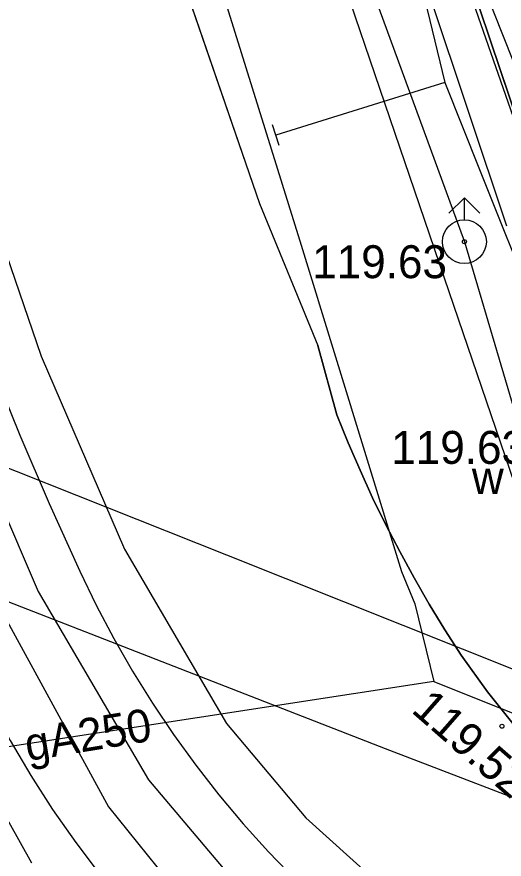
# Model space of a CAD drawing. Extents: x 6432121 to 6432331, y 5662538 to 5662686.
# Drawn here: x 6432274.79 to 6432285.88, y 5662571.21 to 5662590.39 of the extents above; entities that cross this region are included whole.
import ezdxf

# ---------------------------------------------------------------- set-up
doc = ezdxf.new("R2010")
doc.units = 0
for name, color, linetype in [('Warstwa 1', 7, 'Continuous'), ('Warstwa 12', 7, 'Continuous'), ('Warstwa 13', 7, 'Continuous'), ('Warstwa 14', 7, 'Continuous'), ('Warstwa 15', 7, 'Continuous'), ('Warstwa 20', 7, 'Continuous'), ('Warstwa 25', 7, 'Continuous'), ('Warstwa 37', 7, 'Continuous'), ('Warstwa 4', 7, 'Continuous'), ('Warstwa 5', 7, 'Continuous'), ('Warstwa 6', 7, 'Continuous'), ('Warstwa 8', 7, 'Continuous'), ('Warstwa 9', 7, 'Continuous')]:
    doc.layers.add(name, color=color, linetype=linetype)

msp = doc.modelspace()

# ---------------------------------------------------------------- linework, layer by layer
at = {"layer": 'Warstwa 1'}
msp.add_line((6432267.75, 5662642.76), (6432287.64, 5662583.69), dxfattribs=at)
msp.add_line((6432267.75, 5662642.76), (6432287.64, 5662583.69), dxfattribs=at)
at = {"layer": 'Warstwa 12'}
for points in [[(6432259.267, 5662681.053), (6432259.329, 5662671.143), (6432259.331, 5662662.919), (6432260.078, 5662660.682), (6432263.877, 5662649.208), (6432267.527, 5662638.022), (6432271.438, 5662626.054), (6432273.548, 5662619.652), (6432276.516, 5662610.473), (6432279.664, 5662600.926), (6432282.613, 5662591.736), (6432284.976, 5662585.268), (6432286.395, 5662580.459), (6432288.268, 5662574.665)], [(6432288.269, 5662573.47), (6432290.18, 5662576.365), (6432289.651, 5662577.89), (6432283.657, 5662595.089), (6432278.636, 5662609.529), (6432275.228, 5662619.384), (6432273.259, 5662625.008), (6432269.06, 5662637.307), (6432265.455, 5662647.676), (6432262.131, 5662657.28), (6432261.494, 5662659.216), (6432262.228, 5662660.626), (6432262.598, 5662661.472), (6432263.21, 5662662.431), (6432263.592, 5662662.793), (6432265.636, 5662665.038), (6432264.282, 5662671.637), (6432263.631, 5662675.181), (6432263.032, 5662678.117), (6432262.911, 5662681.053)], [(6432258.356, 5662662.998), (6432258.39, 5662658.398), (6432260.508, 5662651.738), (6432262.768, 5662644.481), (6432265.197, 5662636.781), (6432267.384, 5662629.75), (6432269.748, 5662622.257), (6432272.462, 5662613.493), (6432273.441, 5662610.386), (6432276.081, 5662601.737), (6432278.642, 5662593.628), (6432281.263, 5662585.188), (6432283.543, 5662577.76), (6432283.852, 5662577.022), (6432284.284, 5662575.255)], [(6432261.338, 5662662.021), (6432260.831, 5662661.256), (6432261.33, 5662655.003), (6432261.566, 5662651.833), (6432262.397, 5662649.473), (6432263.18, 5662647.177), (6432265.745, 5662639.575), (6432268.331, 5662631.988), (6432271.28, 5662623.264), (6432274.385, 5662614.242), (6432277.778, 5662604.216), (6432280.796, 5662595.387), (6432284.518, 5662584.444), (6432287.071, 5662576.95), (6432288.269, 5662573.47)], [(6432294.644, 5662569.974), (6432292.199, 5662571.213), (6432291.73, 5662571.359), (6432291.554, 5662571.691), (6432290.843, 5662575.72), (6432287.011, 5662587.057), (6432285.41, 5662591.097), (6432281.352, 5662603.627), (6432279.346, 5662609.722), (6432279.211, 5662610.184), (6432279.026, 5662610.616), (6432274.158, 5662623.936), (6432272.237, 5662630.449), (6432265.984, 5662647.596), (6432266.37, 5662648.378)], [(6432273.378, 5662628.56), (6432274.214, 5662626.373), (6432275.936, 5662621.592), (6432276.137, 5662621.121), (6432277.158, 5662615.29), (6432277.656, 5662613.21), (6432277.121, 5662611.091), (6432279.065, 5662604.892), (6432281.714, 5662603.797), (6432281.489, 5662600.828), (6432283.129, 5662594.282), (6432283.903, 5662591.502), (6432284.529, 5662588.89)], [(6432284.529, 5662588.89), (6432280.685, 5662587.694)], [(6432284.529, 5662588.89), (6432285.324, 5662586.912), (6432286.601, 5662583.708), (6432288.192, 5662579.261), (6432289.015, 5662577.532), (6432294.313, 5662575.121), (6432301.928, 5662571.798), (6432305.283, 5662570.247), (6432308.513, 5662568.879)], [(6432288.268, 5662574.665), (6432287.596, 5662574.929), (6432279.572, 5662578.128), (6432271.367, 5662581.39), (6432268.733, 5662580.715)], [(6432268.423, 5662579.446), (6432268.914, 5662579.286), (6432283.177, 5662573.724), (6432291.711, 5662570.445), (6432298.653, 5662567.696), (6432305.047, 5662565.259), (6432317.636, 5662560.353), (6432325.976, 5662557.133)], [(6432284.284, 5662575.255), (6432271.673, 5662573.315), (6432269.061, 5662572.854)], [(6432284.284, 5662575.255), (6432291.672, 5662572.293), (6432300.987, 5662568.554), (6432313.035, 5662563.657), (6432322.464, 5662559.942), (6432325.786, 5662558.712), (6432325.976, 5662558.636)]]:
    msp.add_lwpolyline(points, dxfattribs=at)
at = {"layer": 'Warstwa 14'}
msp.add_circle((6432284.976, 5662585.268), 0.045, dxfattribs=at)
at = {"layer": 'Warstwa 20'}
msp.add_line((6432280.759, 5662587.455), (6432280.611, 5662587.933), dxfattribs=at)
at = {"layer": 'Warstwa 25'}
msp.add_circle((6432285.831, 5662574.233), 0.045, dxfattribs=at)
at = {"layer": 'Warstwa 37'}
for points in [[(6432270.98, 5662592.032), (6432271.449, 5662590.408), (6432271.947, 5662588.793), (6432272.474, 5662587.187), (6432273.03, 5662585.59), (6432273.613, 5662584.003), (6432274.225, 5662582.427), (6432274.865, 5662580.863), (6432275.532, 5662579.309), (6432276.227, 5662577.768)], [(6432276.227, 5662577.768), (6432276.6, 5662576.994), (6432277.001, 5662576.234), (6432277.428, 5662575.489), (6432277.882, 5662574.759), (6432278.361, 5662574.046), (6432278.865, 5662573.35), (6432279.393, 5662572.672), (6432279.945, 5662572.013), (6432280.52, 5662571.375)], [(6432273.41, 5662576.382), (6432273.789, 5662575.542), (6432274.199, 5662574.716), (6432274.639, 5662573.907), (6432275.109, 5662573.114), (6432275.607, 5662572.339), (6432276.134, 5662571.582), (6432276.688, 5662570.846), (6432277.269, 5662570.13), (6432277.876, 5662569.437)], [(6432280.52, 5662571.375), (6432281.172, 5662570.694), (6432281.851, 5662570.041), (6432282.557, 5662569.417), (6432283.288, 5662568.823), (6432284.044, 5662568.259), (6432284.822, 5662567.728), (6432285.621, 5662567.229), (6432286.441, 5662566.763), (6432287.279, 5662566.333)]]:
    msp.add_lwpolyline(points, dxfattribs=at)
at = {"layer": 'Warstwa 4'}
for points in [[(6432284.622, 5662585.914), (6432284.976, 5662586.268)], [(6432285.33, 5662585.914), (6432284.976, 5662586.268)], [(6432284.976, 5662585.768), (6432284.976, 5662586.268)]]:
    msp.add_lwpolyline(points, dxfattribs=at)
msp.add_circle((6432284.976, 5662585.268), 0.5, dxfattribs=at)
at = {"layer": 'Warstwa 5'}
msp.add_line((6432281.622, 5662598.544), (6432285.935, 5662585.632), dxfattribs=at)
at = {"layer": 'Warstwa 6'}
msp.add_lwpolyline([(6432278.892, 5662645.679), (6432279.29, 5662646.39), (6432267.75, 5662642.76), (6432287.64, 5662583.69), (6432294.025, 5662578.332), (6432295.024, 5662576.599), (6432295.196, 5662575.127), (6432301.46, 5662572.69), (6432295.88, 5662579.43), (6432289.26, 5662614.9)], close=True, dxfattribs=at)
for points in [[(6432295.199, 5662556.053), (6432289.811, 5662577.223), (6432287.64, 5662583.69), (6432267.75, 5662642.76), (6432246.69, 5662636.13), (6432263.163, 5662588.197), (6432269.007, 5662560.534), (6432269.756, 5662556.053)], [(6432261.53, 5662642.45), (6432261.725, 5662641.888), (6432263.054, 5662637.661), (6432266.526, 5662627.159), (6432271.921, 5662611.052), (6432274.366, 5662604.334), (6432277.03, 5662595.697), (6432280.318, 5662586.138), (6432281.64, 5662582.902)], [(6432282.071, 5662581.326), (6432281.64, 5662582.902)], [(6432284.904, 5662575.849), (6432284.534, 5662576.428), (6432284.178, 5662577.014), (6432283.835, 5662577.609), (6432283.506, 5662578.211), (6432283.19, 5662578.821), (6432282.889, 5662579.437), (6432282.602, 5662580.061), (6432282.329, 5662580.691), (6432282.071, 5662581.326)], [(6432291.638, 5662569.69), (6432290.756, 5662570.209), (6432289.902, 5662570.773), (6432289.079, 5662571.381), (6432288.289, 5662572.032), (6432287.534, 5662572.722), (6432286.816, 5662573.451), (6432286.137, 5662574.217), (6432285.499, 5662575.017), (6432284.904, 5662575.849)]]:
    msp.add_lwpolyline(points, dxfattribs=at)
at = {"layer": 'Warstwa 8'}
for p, q in [((6432277.03, 5662595.697), (6432280.318, 5662586.138)), ((6432272.015, 5662592.39), (6432275.347, 5662582.659)), ((6432272.015, 5662592.39), (6432275.347, 5662582.659)), ((6432280.318, 5662586.138), (6432281.64, 5662582.902)), ((6432281.64, 5662582.902), (6432282.071, 5662581.326)), ((6432275.347, 5662582.659), (6432277.243, 5662578.265)), ((6432275.347, 5662582.659), (6432277.243, 5662578.265)), ((6432273.307, 5662581.884), (6432275.282, 5662577.299)), ((6432273.307, 5662581.884), (6432275.282, 5662577.299)), ((6432282.071, 5662581.326), (6432282.329, 5662580.691)), ((6432282.329, 5662580.691), (6432282.602, 5662580.061)), ((6432282.602, 5662580.061), (6432282.889, 5662579.437)), ((6432282.889, 5662579.437), (6432283.19, 5662578.821)), ((6432283.19, 5662578.821), (6432283.506, 5662578.211)), ((6432277.243, 5662578.265), (6432279.565, 5662574.297)), ((6432277.243, 5662578.265), (6432279.565, 5662574.297)), ((6432283.506, 5662578.211), (6432283.835, 5662577.609)), ((6432283.835, 5662577.609), (6432284.178, 5662577.014)), ((6432275.282, 5662577.299), (6432277.79, 5662573.009)), ((6432275.282, 5662577.299), (6432277.79, 5662573.009)), ((6432284.178, 5662577.014), (6432284.534, 5662576.428)), ((6432274.436, 5662576.88), (6432276.882, 5662572.4)), ((6432274.436, 5662576.88), (6432276.882, 5662572.4)), ((6432284.534, 5662576.428), (6432284.904, 5662575.849)), ((6432272.415, 5662575.974), (6432275.126, 5662571.121)), ((6432272.415, 5662575.974), (6432275.126, 5662571.121)), ((6432284.904, 5662575.849), (6432285.499, 5662575.017)), ((6432285.499, 5662575.017), (6432286.137, 5662574.217)), ((6432279.565, 5662574.297), (6432281.369, 5662572.145)), ((6432279.565, 5662574.297), (6432281.369, 5662572.145)), ((6432277.79, 5662573.009), (6432279.761, 5662570.684)), ((6432277.79, 5662573.009), (6432279.761, 5662570.684)), ((6432276.882, 5662572.4), (6432278.685, 5662570.157)), ((6432276.882, 5662572.4), (6432278.685, 5662570.157)), ((6432281.369, 5662572.145), (6432284.396, 5662569.428)), ((6432281.369, 5662572.145), (6432284.396, 5662569.428))]:
    msp.add_line(p, q, dxfattribs=at)
at = {"layer": 'Warstwa 9'}
for p, q in [((6432281.622, 5662598.544), (6432285.935, 5662585.632)), ((6432277.03, 5662595.697), (6432280.318, 5662586.138)), ((6432280.318, 5662586.138), (6432281.64, 5662582.902)), ((6432281.64, 5662582.902), (6432282.071, 5662581.326)), ((6432282.071, 5662581.326), (6432282.329, 5662580.691)), ((6432282.329, 5662580.691), (6432282.602, 5662580.061)), ((6432282.602, 5662580.061), (6432282.889, 5662579.437)), ((6432282.889, 5662579.437), (6432283.19, 5662578.821)), ((6432283.19, 5662578.821), (6432283.506, 5662578.211)), ((6432283.506, 5662578.211), (6432283.835, 5662577.609)), ((6432283.835, 5662577.609), (6432284.178, 5662577.014)), ((6432284.178, 5662577.014), (6432284.534, 5662576.428)), ((6432284.534, 5662576.428), (6432284.904, 5662575.849)), ((6432284.904, 5662575.849), (6432285.499, 5662575.017)), ((6432285.499, 5662575.017), (6432286.137, 5662574.217))]:
    msp.add_line(p, q, dxfattribs=at)

# ---------------------------------------------------------------- texts
at = {"layer": 'Warstwa 13'}
msp.add_text('gA250', height=0.75, rotation=9.4423, dxfattribs=at).set_placement((6432275.041, 5662573.434))
at = {"layer": 'Warstwa 15'}
for p in [(6432281.513, 5662584.437), (6432283.312, 5662580.208)]:
    msp.add_text('119.63', height=0.75, dxfattribs=at).set_placement(p)
at = {"layer": 'Warstwa 25'}
msp.add_text('119.52', height=0.75, rotation=318.788, dxfattribs=at).set_placement((6432283.744, 5662574.57))
at = {"layer": 'Warstwa 5'}
msp.add_text('w', height=0.75, dxfattribs=at).set_placement((6432285.147, 5662579.52))

doc.saveas('drawing.dxf')
